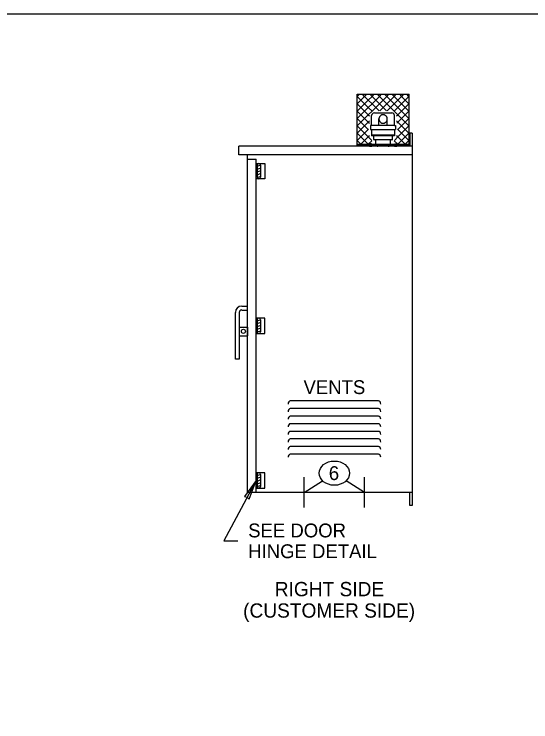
# Model space of a CAD drawing. Extents: x 99862 to 103680, y 99470 to 105076.
# Drawn here: x 101043 to 101639, y 101258 to 102076 of the extents above; entities that cross this region are included whole.
import ezdxf

# ---------------------------------------------------------------- set-up
doc = ezdxf.new("R2010")
doc.units = 0
for name, color, linetype in [('Level 1', 7, 'Continuous'), ('Level 11', 7, 'Continuous'), ('Level 15', 7, 'Continuous'), ('Level 20', 7, 'Continuous'), ('Level 40', 7, 'Continuous')]:
    doc.layers.add(name, color=color, linetype=linetype)

msp = doc.modelspace()

# ---------------------------------------------------------------- linework, layer by layer
at = {"layer": 'Level 1'}
for p, q in [((101438.48, 101925.19), (101438.48, 101982.95)), ((101438.48, 101982.94), (101498.48, 101982.94)), ((101438.48, 101980.71), (101438.7, 101980.49)), ((101438.7, 101980.49), (101438.48, 101980.27)), ((101438.7, 101980.49), (101441.16, 101982.94)), ((101442.96, 101976.24), (101438.7, 101980.49)), ((101447.21, 101980.49), (101442.96, 101976.24)), ((101447.21, 101980.49), (101444.76, 101982.94)), ((101449.66, 101982.94), (101447.21, 101980.49)), ((101451.47, 101976.24), (101447.21, 101980.49)), ((101455.72, 101980.49), (101451.47, 101976.24)), ((101453.27, 101982.94), (101455.72, 101980.49)), ((101455.72, 101980.49), (101458.17, 101982.94)), ((101459.98, 101976.24), (101455.72, 101980.49)), ((101464.23, 101980.49), (101459.98, 101976.24)), ((101461.78, 101982.94), (101464.23, 101980.49)), ((101464.23, 101980.49), (101466.68, 101982.94)), ((101468.48, 101976.24), (101464.23, 101980.49)), ((101472.74, 101980.49), (101468.48, 101976.24)), ((101470.29, 101982.94), (101472.74, 101980.49)), ((101472.74, 101980.49), (101475.19, 101982.94)), ((101476.99, 101976.24), (101472.74, 101980.49)), ((101481.25, 101980.49), (101476.99, 101976.24)), ((101478.79, 101982.94), (101481.25, 101980.49)), ((101481.25, 101980.49), (101483.7, 101982.94)), ((101485.5, 101976.24), (101481.25, 101980.49)), ((101489.75, 101980.49), (101485.5, 101976.24)), ((101487.3, 101982.94), (101489.75, 101980.49)), ((101492.21, 101982.94), (101489.75, 101980.49)), ((101489.75, 101980.49), (101494.01, 101976.24)), ((101494.01, 101976.24), (101498.26, 101980.49)), ((101498.26, 101980.49), (101495.81, 101982.94)), ((101498.48, 101980.71), (101498.26, 101980.49)), ((101498.26, 101980.49), (101498.48, 101980.27)), ((101498.48, 101925.19), (101498.48, 101982.94)), ((101438.48, 101972.2), (101438.7, 101971.98)), ((101438.7, 101971.98), (101438.48, 101971.76)), ((101438.7, 101971.98), (101442.96, 101976.24)), ((101442.96, 101967.73), (101438.7, 101971.98)), ((101442.96, 101976.24), (101447.21, 101971.98)), ((101447.21, 101971.98), (101442.96, 101967.73)), ((101447.21, 101971.98), (101451.47, 101976.24)), ((101451.47, 101967.73), (101447.21, 101971.98)), ((101451.47, 101976.24), (101455.72, 101971.98)), ((101455.72, 101971.98), (101451.47, 101967.73)), ((101455.72, 101971.98), (101459.98, 101976.24)), ((101459.98, 101967.73), (101455.72, 101971.98)), ((101459.98, 101976.24), (101464.23, 101971.98)), ((101464.23, 101971.98), (101459.98, 101967.73)), ((101464.23, 101971.98), (101468.48, 101976.24)), ((101468.48, 101967.73), (101464.23, 101971.98)), ((101468.48, 101976.24), (101472.74, 101971.98)), ((101472.74, 101971.98), (101468.48, 101967.73)), ((101472.74, 101971.98), (101476.99, 101976.24)), ((101476.99, 101967.73), (101472.74, 101971.98)), ((101476.99, 101976.24), (101481.25, 101971.98)), ((101481.25, 101971.98), (101476.99, 101967.73)), ((101481.25, 101971.98), (101485.5, 101976.24)), ((101485.5, 101967.73), (101481.25, 101971.98)), ((101485.5, 101976.24), (101489.75, 101971.98)), ((101489.75, 101971.98), (101485.5, 101967.73)), ((101494.01, 101976.24), (101489.75, 101971.98)), ((101489.75, 101971.98), (101494.01, 101967.73)), ((101498.26, 101971.98), (101494.01, 101976.24)), ((101494.01, 101967.73), (101498.26, 101971.98)), ((101498.48, 101972.21), (101498.26, 101971.98)), ((101498.26, 101971.98), (101498.48, 101971.76)), ((101438.48, 101963.7), (101438.7, 101963.48)), ((101438.7, 101963.48), (101438.48, 101963.26)), ((101438.7, 101963.48), (101442.96, 101967.73)), ((101442.96, 101959.22), (101438.7, 101963.48)), ((101442.96, 101967.73), (101447.21, 101963.48)), ((101447.21, 101963.48), (101442.96, 101959.22)), ((101447.21, 101963.48), (101451.47, 101967.73)), ((101451.47, 101959.22), (101447.21, 101963.48)), ((101451.47, 101967.73), (101455.72, 101963.48)), ((101455.72, 101963.48), (101451.47, 101959.22)), ((101455.72, 101963.48), (101459.98, 101967.73)), ((101455.94, 101963.26), (101455.72, 101963.48)), ((101459.98, 101967.73), (101463.85, 101963.86)), ((101464.61, 101963.86), (101468.48, 101967.73)), ((101468.48, 101967.73), (101472.36, 101963.86)), ((101473.12, 101963.86), (101476.99, 101967.73)), ((101476.99, 101967.73), (101481.25, 101963.48)), ((101481.25, 101963.48), (101481.03, 101963.26)), ((101481.25, 101963.48), (101485.5, 101967.73)), ((101485.5, 101959.22), (101481.25, 101963.48)), ((101485.5, 101967.73), (101489.75, 101963.48)), ((101489.75, 101963.48), (101485.5, 101959.22)), ((101494.01, 101967.73), (101489.75, 101963.48)), ((101489.75, 101963.48), (101494.01, 101959.22)), ((101498.26, 101963.48), (101494.01, 101967.73)), ((101494.01, 101959.22), (101498.26, 101963.48)), ((101498.48, 101963.7), (101498.26, 101963.48)), ((101498.26, 101963.48), (101498.48, 101963.25)), ((101438.48, 101955.19), (101438.7, 101954.97)), ((101438.7, 101954.97), (101438.48, 101954.75)), ((101438.7, 101954.97), (101442.96, 101959.22)), ((101442.96, 101950.71), (101438.7, 101954.97)), ((101442.96, 101959.22), (101447.21, 101954.97)), ((101447.21, 101954.97), (101442.96, 101950.71)), ((101447.21, 101954.97), (101451.47, 101959.22)), ((101451.47, 101950.71), (101447.21, 101954.97)), ((101451.47, 101959.22), (101452.84, 101957.85)), ((101455.25, 101947.01), (101455.25, 101958.24)), ((101458.46, 101961.45), (101478.51, 101961.45)), ((101463.67, 101947.01), (101463.67, 101954.39)), ((101473.3, 101947.01), (101473.3, 101954.39)), ((101481.72, 101947.01), (101481.72, 101958.24)), ((101484.13, 101957.85), (101485.5, 101959.22)), ((101485.5, 101959.22), (101489.75, 101954.97)), ((101489.75, 101954.97), (101485.5, 101950.71)), ((101494.01, 101959.22), (101489.75, 101954.97)), ((101489.75, 101954.97), (101494.01, 101950.71)), ((101498.26, 101954.97), (101494.01, 101959.22)), ((101494.01, 101950.71), (101498.26, 101954.97)), ((101498.48, 101955.19), (101498.26, 101954.97)), ((101498.26, 101954.97), (101498.48, 101954.75)), ((101438.48, 101946.68), (101438.7, 101946.46)), ((101438.7, 101946.46), (101438.48, 101946.24)), ((101438.7, 101946.46), (101442.96, 101950.71)), ((101442.96, 101942.2), (101438.7, 101946.46)), ((101442.96, 101950.71), (101447.21, 101946.46)), ((101447.21, 101946.46), (101442.96, 101942.2)), ((101447.21, 101946.46), (101451.47, 101950.71)), ((101451.47, 101942.2), (101447.21, 101946.46)), ((101452.84, 101952.09), (101451.47, 101950.71)), ((101451.47, 101950.71), (101452.76, 101949.42)), ((101455.25, 101947.01), (101454.04, 101947.01)), ((101454.04, 101947.01), (101454.04, 101942.2)), ((101481.72, 101947.01), (101455.25, 101947.01)), ((101481.72, 101947.01), (101482.92, 101947.01)), ((101482.92, 101947.01), (101482.92, 101942.2)), ((101485.5, 101950.71), (101484.13, 101952.09)), ((101484.2, 101949.42), (101485.5, 101950.71)), ((101485.5, 101950.71), (101489.75, 101946.46)), ((101489.75, 101946.46), (101485.5, 101942.2)), ((101494.01, 101950.71), (101489.75, 101946.46)), ((101489.75, 101946.46), (101494.01, 101942.2)), ((101498.26, 101946.46), (101494.01, 101950.71)), ((101494.01, 101942.2), (101498.26, 101946.46)), ((101498.48, 101946.68), (101498.26, 101946.46)), ((101498.26, 101946.46), (101498.48, 101946.24)), ((101438.48, 101938.17), (101438.7, 101937.95)), ((101438.7, 101937.95), (101438.48, 101937.73)), ((101438.7, 101937.95), (101442.96, 101942.2)), ((101442.96, 101933.7), (101438.7, 101937.95)), ((101442.96, 101942.2), (101447.21, 101937.95)), ((101447.21, 101937.95), (101442.96, 101933.7)), ((101447.21, 101937.95), (101451.47, 101942.2)), ((101451.47, 101933.7), (101447.21, 101937.95)), ((101451.64, 101942.38), (101451.47, 101942.2)), ((101451.47, 101942.2), (101451.64, 101942.03)), ((101454.04, 101942.2), (101482.92, 101942.2)), ((101455.25, 101942.2), (101455.25, 101934.98)), ((101481.72, 101942.2), (101481.72, 101934.98)), ((101485.5, 101942.2), (101485.33, 101942.38)), ((101485.33, 101942.03), (101485.5, 101942.2)), ((101485.5, 101942.2), (101489.75, 101937.95)), ((101489.75, 101937.95), (101485.5, 101933.7)), ((101494.01, 101942.2), (101489.75, 101937.95)), ((101489.75, 101937.95), (101494.01, 101933.7)), ((101498.26, 101937.95), (101494.01, 101942.2)), ((101494.01, 101933.7), (101498.26, 101937.95)), ((101498.48, 101938.17), (101498.26, 101937.95)), ((101498.26, 101937.95), (101498.48, 101937.73)), ((101438.48, 101929.66), (101438.7, 101929.44)), ((101438.7, 101929.44), (101442.96, 101933.7)), ((101442.96, 101933.7), (101447.21, 101929.44)), ((101447.21, 101929.44), (101451.47, 101933.7)), ((101452.84, 101935.07), (101451.47, 101933.7)), ((101451.47, 101933.7), (101455.43, 101929.73)), ((101481.72, 101935.58), (101455.25, 101935.58)), ((101481.72, 101934.98), (101455.25, 101934.98)), ((101457.65, 101930.77), (101457.65, 101934.98)), ((101478.71, 101930.16), (101458.26, 101930.16)), ((101460.06, 101925.35), (101460.06, 101930.16)), ((101476.91, 101925.35), (101476.91, 101930.16)), ((101479.31, 101930.77), (101479.31, 101934.98)), ((101481.54, 101929.73), (101485.5, 101933.7)), ((101485.5, 101933.7), (101484.13, 101935.07)), ((101485.5, 101933.7), (101489.75, 101929.44)), ((101494.01, 101933.7), (101489.75, 101929.44)), ((101498.26, 101929.44), (101494.01, 101933.7)), ((101498.48, 101929.66), (101498.26, 101929.44)), ((101438.7, 101929.44), (101438.48, 101929.22)), ((101438.48, 101925.19), (101498.48, 101925.19)), ((101438.48, 101924.15), (101438.48, 101925.09)), ((101438.48, 101925.09), (101498.48, 101925.09)), ((101438.48, 101924.15), (101498.48, 101924.15)), ((101442.96, 101925.19), (101438.7, 101929.44)), ((101447.21, 101929.44), (101442.96, 101925.19)), ((101451.47, 101925.19), (101447.21, 101929.44)), ((101455.61, 101929.33), (101451.47, 101925.19)), ((101474.5, 101922.94), (101462.47, 101922.94)), ((101485.5, 101925.19), (101481.36, 101929.33)), ((101489.75, 101929.44), (101485.5, 101925.19)), ((101489.75, 101929.44), (101494.01, 101925.19)), ((101494.01, 101925.19), (101498.26, 101929.44)), ((101498.26, 101929.44), (101498.48, 101929.22)), ((101498.48, 101924.15), (101498.48, 101925.09)), ((101321.98, 101885.1), (101321.98, 101902.87)), ((101322.98, 101900.87), (101322.98, 101887.1)), ((101326.98, 101900.87), (101322.98, 101899.33)), ((101326.98, 101897.66), (101322.98, 101896.11)), ((101326.98, 101900.87), (101326.98, 101887.1)), ((101326.98, 101894.44), (101322.98, 101892.9)), ((101326.98, 101891.23), (101322.98, 101889.68)), ((101326.98, 101888.01), (101323.08, 101886.5)), ((101305.25, 101738.17), (101311.98, 101738.17)), ((101305.25, 101733.73), (101311.98, 101733.73)), ((101298, 101676.86), (101298, 101730.92)), ((101302.43, 101730.92), (101302.43, 101676.86)), ((101321.98, 101724.33), (101321.98, 101706.56)), ((101322.98, 101722.33), (101322.98, 101708.56)), ((101326.98, 101722.33), (101322.98, 101720.79)), ((101326.98, 101719.11), (101322.98, 101717.57)), ((101326.98, 101722.33), (101326.98, 101708.56)), ((101302.43, 101714.07), (101311.98, 101714.07)), ((101311.98, 101714.07), (101311.98, 101704.07)), ((101326.98, 101715.9), (101322.98, 101714.36)), ((101326.98, 101712.68), (101322.98, 101711.14)), ((101326.98, 101709.47), (101323.08, 101707.96)), ((101302.43, 101704.07), (101311.98, 101704.07)), ((101302.43, 101676.86), (101298, 101676.86)), ((101321.98, 101545.79), (101321.98, 101528.02)), ((101322.98, 101543.79), (101322.98, 101530.02)), ((101326.98, 101543.79), (101322.98, 101542.24)), ((101326.98, 101540.57), (101322.98, 101539.03)), ((101326.98, 101537.36), (101322.98, 101535.81)), ((101326.98, 101543.79), (101326.98, 101530.02)), ((101326.98, 101534.14), (101322.98, 101532.6)), ((101326.98, 101530.93), (101323.08, 101529.42))]:
    msp.add_line(p, q, dxfattribs=at)
msp.add_lwpolyline([(99862, 99999.5), (103151, 99999.5), (103151, 102075.5), (99862, 102075.5)], close=True, dxfattribs=at)
for points in [[(101321.98, 101902.87), (101331.98, 101902.87), (101331.98, 101885.1), (101321.98, 101885.1)], [(101321.98, 101706.56), (101331.98, 101706.56), (101331.98, 101724.33), (101321.98, 101724.33)], [(101321.98, 101528.02), (101331.98, 101528.02), (101331.98, 101545.79), (101321.98, 101545.79)]]:
    msp.add_lwpolyline(points, dxfattribs=at)
msp.add_circle((101307.21, 101709.07), 2.37, dxfattribs=at)
for centre, radius, start, end in [((101458.46, 101958.24), 3.21, 90, 180), ((101468.48, 101954.39), 4.81, 0, 180.00029), ((101468.48, 101954.39), 4.81, 179.99971, 360), ((101478.51, 101958.24), 3.21, 0, 90), ((101458.26, 101930.77), 0.602, 180, 270), ((101478.71, 101930.77), 0.602, 270, 0), ((101462.47, 101925.35), 2.41, 180, 270), ((101474.5, 101925.35), 2.41, 270, 0), ((101324.98, 101900.87), 2, 90, 180), ((101324.98, 101900.87), 2, 0, 90), ((101324.98, 101887.1), 2, 180, 270), ((101324.98, 101887.1), 2, 270, 0), ((101305.25, 101730.92), 7.25, 90, 180), ((101305.25, 101730.92), 2.82, 90, 180), ((101324.98, 101722.33), 2, 90, 180), ((101324.98, 101722.33), 2, 0, 90), ((101324.98, 101708.56), 2, 180, 270), ((101324.98, 101708.56), 2, 270, 0), ((101324.98, 101543.79), 2, 90, 180), ((101324.98, 101543.79), 2, 0, 90), ((101324.98, 101530.02), 2, 180, 270), ((101324.98, 101530.02), 2, 270, 0)]:
    msp.add_arc(centre, radius, start, end, dxfattribs=at)
at = {"layer": 'Level 11'}
for p, q in [((101463.17, 101628.62), (101361.35, 101628.62)), ((101463.17, 101619.85), (101361.35, 101619.85)), ((101463.17, 101611.09), (101361.35, 101611.09)), ((101463.17, 101602.33), (101361.35, 101602.33)), ((101463.17, 101593.56), (101361.35, 101593.56)), ((101463.17, 101584.8), (101361.35, 101584.8)), ((101463.17, 101576.04), (101361.35, 101576.04)), ((101463.17, 101567.27), (101361.35, 101567.27))]:
    msp.add_line(p, q, dxfattribs=at)
for centre, start_param, end_param in [((101361.35, 101624.98), 0, 1.570796), ((101463.17, 101624.98), 4.712389, 6.283185), ((101361.35, 101616.22), 0, 1.570796), ((101463.17, 101616.22), 4.712389, 6.283185), ((101361.35, 101607.45), 0, 1.570796), ((101463.17, 101607.45), 4.712389, 6.283185), ((101361.35, 101598.69), 0, 1.570796), ((101463.17, 101598.69), 4.712389, 6.283185), ((101361.35, 101589.93), 0, 1.570796), ((101463.17, 101589.93), 4.712389, 6.283185), ((101361.35, 101581.16), 0, 1.570796), ((101463.17, 101581.16), 4.712389, 6.283185), ((101361.35, 101572.4), 0, 1.570796), ((101463.17, 101572.4), 4.712389, 6.283185), ((101361.35, 101563.63), 0, 1.570796), ((101463.17, 101563.63), 4.712389, 6.283185)]:
    msp.add_ellipse(centre, major_axis=(0, 3.64), ratio=0.707107, start_param=start_param, end_param=end_param, dxfattribs=at)
at = {"layer": 'Level 15'}
for p, q in [((101501.98, 101937.94), (101499.48, 101937.94)), ((101499.48, 101937.94), (101499.48, 101922.94)), ((101501.98, 101912.94), (101301.98, 101912.94)), ((101311.98, 101907.94), (101321.98, 101907.94)), ((101321.98, 101522.94), (101321.98, 101907.94)), ((101377.53, 101505.44), (101377.53, 101540.44)), ((101446.98, 101505.44), (101446.98, 101540.44)), ((101321.98, 101536.9), (101284.74, 101467.06)), ((101377.53, 101522.94), (101398.62, 101536.5)), ((101446.98, 101522.94), (101425.9, 101536.5)), ((101499.48, 101507.94), (101499.48, 101522.94)), ((101501.98, 101507.94), (101499.48, 101507.94)), ((101284.74, 101467.06), (101300.74, 101467.06))]:
    msp.add_line(p, q, dxfattribs=at)
msp.add_lwpolyline([(101321.98, 101536.9), (101308.61, 101518.16), (101311.74, 101517.69), (101313.88, 101515.35)], close=True, dxfattribs=at)
at = {"layer": 'Level 20'}
msp.add_ellipse((101412.26, 101545.27), major_axis=(-17.5, 0), ratio=0.8, dxfattribs=at)
at = {"layer": 'Level 40'}
for p, q in [((101501.98, 101937.94), (101501.98, 101507.94)), ((101501.98, 101922.94), (101301.98, 101922.94)), ((101301.98, 101912.94), (101301.98, 101922.94)), ((101311.98, 101522.94), (101311.98, 101912.94)), ((101501.98, 101522.94), (101311.98, 101522.94))]:
    msp.add_line(p, q, dxfattribs=at)
for points in [[(101455.39, 101923.19), (101455.39, 101922.94), (101452.7, 101922.94), (101452.7, 101923.19)], [(101455.36, 101923.35), (101455.36, 101923.19), (101452.73, 101923.19), (101452.73, 101923.35)], [(101455.03, 101925.11), (101455.03, 101925.88), (101453.06, 101925.88), (101453.06, 101925.11)], [(101455.03, 101923.35), (101455.03, 101924.15), (101453.06, 101924.15), (101453.06, 101923.35)], [(101481.58, 101923.19), (101481.58, 101922.94), (101484.27, 101922.94), (101484.27, 101923.19)], [(101481.61, 101923.35), (101481.61, 101923.19), (101484.24, 101923.19), (101484.24, 101923.35)], [(101481.94, 101925.11), (101481.94, 101925.88), (101483.91, 101925.88), (101483.91, 101925.11)], [(101481.94, 101923.35), (101481.94, 101924.15), (101483.91, 101924.15), (101483.91, 101923.35)]]:
    msp.add_lwpolyline(points, close=True, dxfattribs=at)

# ---------------------------------------------------------------- texts
at = {"layer": 'Level 20'}
msp.add_text('VENTS', height=16, rotation=360, dxfattribs=at).set_placement((101376.64, 101636.62))
for s, height, p in [('6', 16, (101405.83, 101537.27)), ('SEE DOOR', 16, (101312.74, 101471.06)), ('HINGE DETAIL', 16, (101312.74, 101447.06)), ('RIGHT SIDE', 16.5, (101343.48, 101403.07)), ('(CUSTOMER SIDE)', 16.5, (101306.9, 101378.32))]:
    msp.add_text(s, height=height, dxfattribs=at).set_placement(p)

doc.saveas('drawing.dxf')
